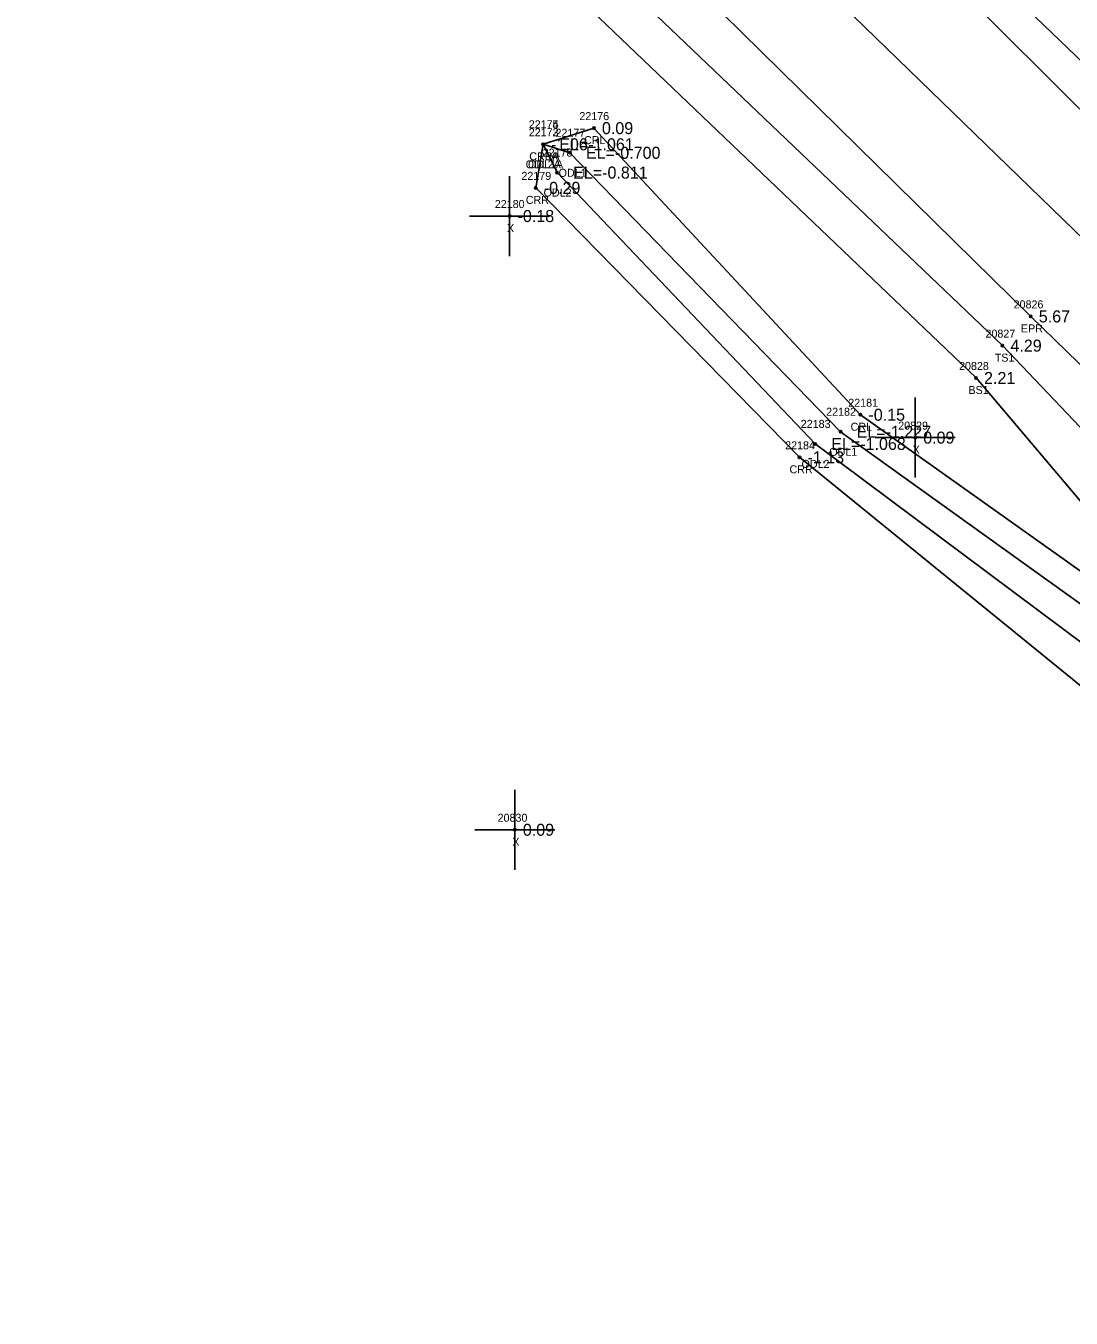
# Model space of a CAD drawing. Extents: x 2608745 to 2610333, y 641917 to 643463.
# Drawn here: x 2609277.1 to 2609407.7, y 642665.2 to 642826.6 of the extents above; entities that cross this region are included whole.
import ezdxf

# ---------------------------------------------------------------- set-up
doc = ezdxf.new("R2010")
doc.units = 0
for name, color, linetype in [('RD_DTM_BkLn1', 7, 'Continuous'), ('RD_DTM_BkLn2', 7, 'Continuous'), ('RD_DTM_BkLn_txCode', 7, 'Continuous'), ('RD_EX_H2O', 7, 'Continuous'), ('RD_EX_H2O_txCode', 7, 'Continuous'), ('RD_EX_Misc', 7, 'Continuous'), ('RD_EX_Misc_txCode', 7, 'Continuous'), ('RD_EX_Road', 7, 'Continuous'), ('RD_EX_Road_txCode', 7, 'Continuous'), ('RD_EX_TX_H2O_ELEV', 7, 'Continuous'), ('RD_EX_TX_Misc_ELEV', 7, 'Continuous'), ('RD_EX_TX_Road_ELEV', 7, 'Continuous'), ('RD_SMD_Locator', 7, 'Continuous')]:
    doc.layers.add(name, color=color, linetype=linetype)

msp = doc.modelspace()

# ---------------------------------------------------------------- linework, layer by layer
at = {"layer": 'RD_DTM_BkLn1'}
msp.add_lwpolyline([(2608814.73, 643373.65), (2608890.45, 643300.26), (2608962.19, 643231.31), (2609034.91, 643161.19), (2609108.48, 643089.9), (2609179.19, 643022.29), (2609255.71, 642948.78), (2609335.19, 642871.73), (2609410.7, 642798.48), (2609491.67, 642719.95), (2609518.07, 642695.15)], dxfattribs=at)
at = {"layer": 'RD_DTM_BkLn2'}
for points in [[(2609298.5, 642957.84), (2609303.58, 642944.57), (2609301.78, 642940.67), (2609288.09, 642950.22), (2609286.42, 642948.37), (2609286.98, 642943.32), (2609297.07, 642935.45), (2609305.3, 642928.41), (2609313.77, 642918.5), (2609346.23, 642882.3), (2609422.21, 642809.45), (2609480.56, 642755.4), (2609506.75, 642733.83), (2609516.79, 642724.84), (2609528.1, 642713.09), (2609531.25, 642709.73), (2609532.97, 642706.82)], [(2609261.87, 642916.52), (2609266.58, 642914.91), (2609285.18, 642896.17), (2609323.43, 642858.86), (2609399.07, 642786.65), (2609450.77, 642732.34), (2609478.69, 642705.43), (2609489.94, 642696.01), (2609499.39, 642685.95), (2609506.29, 642680.17), (2609532.97, 642706.82)], [(2609260.59, 642912.35), (2609267.04, 642908.29), (2609268.14, 642909.06), (2609282.93, 642892.55), (2609320.01, 642855.03), (2609395.77, 642782.61), (2609444.33, 642725.24)]]:
    msp.add_lwpolyline(points, dxfattribs=at)
at = {"layer": 'RD_EX_H2O'}
for points in [[(2609341.7, 642811.8), (2609348.04, 642813.82), (2609381.33, 642778.02), (2609418.14, 642751.86), (2609444.33, 642725.24), (2609470.95, 642698.08), (2609498.28, 642669.79)], [(2609341.7, 642811.8), (2609340.78, 642806.36), (2609373.72, 642772.7), (2609409.62, 642743.52), (2609461.2, 642683.86), (2609477.32, 642664.29)], [(2609341.7, 642811.8), (2609343.44, 642808.27), (2609375.68, 642774.38), (2609412.81, 642746.64), (2609463.49, 642686.63), (2609487.77, 642666.13)], [(2609341.7, 642811.8), (2609345.04, 642810.74), (2609378.85, 642775.89), (2609415.34, 642749.68), (2609465.85, 642691.72), (2609492.22, 642666.66)]]:
    msp.add_lwpolyline(points, dxfattribs=at)
at = {"layer": 'RD_EX_Misc'}
for p, q in [((2609337.5, 642797.84), (2609337.5, 642807.84)), ((2609332.5, 642802.84), (2609342.5, 642802.84)), ((2609388.17, 642770.16), (2609388.17, 642780.16)), ((2609383.17, 642775.16), (2609393.17, 642775.16)), ((2609338.16, 642721.18), (2609338.16, 642731.18)), ((2609333.16, 642726.18), (2609343.16, 642726.18))]:
    msp.add_line(p, q, dxfattribs=at)
at = {"layer": 'RD_EX_Road'}
for points in [[(2608806.89, 643364.99), (2608810.18, 643361.1), (2608820.75, 643351.25), (2608881.81, 643292.24), (2608917.83, 643257.49), (2608933.21, 643242.71), (2608954.07, 643222.83), (2609026.06, 643154.19), (2609039.6, 643139.96), (2609073.88, 643106.95), (2609100.48, 643081.89), (2609124.19, 643058.87), (2609171.61, 643013.71), (2609183.19, 643002.28), (2609197.91, 642988.37), (2609247.59, 642940.95), (2609328.02, 642863.6), (2609402.61, 642790.3), (2609474.23, 642720.69), (2609483.84, 642711.58), (2609495.78, 642699.92), (2609509.81, 642686.45)], [(2609058.51, 643155.46), (2609096.06, 643119.37), (2609116.51, 643099.11), (2609162.4, 643055.35), (2609177.21, 643041.34), (2609188.35, 643030.96), (2609199.91, 643019.76), (2609205.8, 643014.04), (2609217.13, 643003.17), (2609235.83, 642983.9), (2609237.03, 642983.51), (2609256.8, 642965.04), (2609258.49, 642962.51), (2609263.65, 642957.66), (2609344.71, 642879.89), (2609418.83, 642806.19), (2609500.61, 642728.46), (2609512.38, 642716.82), (2609526.19, 642703.5)]]:
    msp.add_lwpolyline(points, dxfattribs=at)
at = {"layer": 'RD_SMD_Locator'}
for centre in [(2609348.04, 642813.82), (2609341.7, 642811.8), (2609341.7, 642811.8), (2609341.7, 642811.8), (2609341.7, 642811.8), (2609345.04, 642810.74), (2609343.44, 642808.27), (2609340.78, 642806.36), (2609337.5, 642802.84), (2609402.61, 642790.3), (2609399.07, 642786.65), (2609395.77, 642782.61), (2609381.33, 642778.02), (2609378.85, 642775.89), (2609375.68, 642774.38), (2609388.17, 642775.16), (2609373.72, 642772.7), (2609338.16, 642726.18)]:
    msp.add_circle(centre, 0.15, dxfattribs=at)

# ---------------------------------------------------------------- texts
at = {"layer": 'RD_DTM_BkLn_txCode'}
for s, p in [('20827', (2609396.95, 642787.65)), ('20828', (2609393.65, 642783.61)), ('TS1', (2609398.11, 642784.65)), ('BS1', (2609394.82, 642780.61))]:
    msp.add_text(s, height=1, dxfattribs=at).set_placement(p)
at = {"layer": 'RD_EX_H2O_txCode'}
for s, p in [('22174', (2609339.9, 642813.8)), ('22175', (2609339.9, 642813.8)), ('22176', (2609346.22, 642814.82)), ('22172', (2609339.9, 642812.8)), ('22173', (2609339.9, 642812.8)), ('22177', (2609343.24, 642812.74)), ('CRL', (2609346.81, 642811.82)), ('CRRA', (2609339.96, 642809.8)), ('CRLA', (2609339.98, 642809.8)), ('22178', (2609341.64, 642810.27)), ('22179', (2609338.98, 642807.36)), ('ODL2A', (2609339.52, 642808.8)), ('ODL1A', (2609339.8, 642808.8)), ('ODL1', (2609343.63, 642807.74)), ('CRR', (2609339.53, 642804.36)), ('ODL2', (2609341.75, 642805.27)), ('22181', (2609379.81, 642779.02)), ('22182', (2609377.05, 642777.89)), ('22183', (2609373.88, 642776.38)), ('CRL', (2609380.1, 642776.02)), ('22184', (2609371.93, 642773.7)), ('ODL1', (2609377.44, 642772.89)), ('CRR', (2609372.47, 642770.7)), ('ODL2', (2609373.98, 642771.38))]:
    msp.add_text(s, height=1, dxfattribs=at).set_placement(p)
at = {"layer": 'RD_EX_Misc_txCode'}
for s, p in [('22180', (2609335.66, 642803.84)), ('X', (2609337.18, 642800.84)), ('20829', (2609386.05, 642776.16)), ('X', (2609387.85, 642773.16)), ('20830', (2609336.01, 642727.18)), ('X', (2609337.85, 642724.18))]:
    msp.add_text(s, height=1, dxfattribs=at).set_placement(p)
at = {"layer": 'RD_EX_Road_txCode'}
for s, p in [('20826', (2609400.47, 642791.3)), ('EPR', (2609401.38, 642788.3))]:
    msp.add_text(s, height=1, dxfattribs=at).set_placement(p)
at = {"layer": 'RD_EX_TX_H2O_ELEV'}
for s, p in [('0.09', (2609349.04, 642813.07)), ('-1.06', (2609342.7, 642811.05)), ('-1.06', (2609342.7, 642811.05)), ('EL=-1.061', (2609343.7, 642811.05)), ('EL=-1.061', (2609343.7, 642811.05)), ('EL=-0.700', (2609347.04, 642809.99)), ('EL=-0.811', (2609345.44, 642807.52)), ('-0.29', (2609341.78, 642805.61)), ('-0.15', (2609382.33, 642777.27)), ('EL=-1.227', (2609380.85, 642775.14)), ('EL=-1.068', (2609377.68, 642773.63)), ('-1.13', (2609374.72, 642771.95))]:
    msp.add_text(s, height=1.5, dxfattribs=at).set_placement(p)
at = {"layer": 'RD_EX_TX_Misc_ELEV'}
for s, p in [('-0.18', (2609338.5, 642802.09)), ('4.29', (2609400.07, 642785.9)), ('2.21', (2609396.77, 642781.86)), ('0.09', (2609389.17, 642774.41)), ('0.09', (2609339.16, 642725.43))]:
    msp.add_text(s, height=1.5, dxfattribs=at).set_placement(p)
at = {"layer": 'RD_EX_TX_Road_ELEV'}
msp.add_text('5.67', height=1.5, dxfattribs=at).set_placement((2609403.61, 642789.55))

doc.saveas('drawing.dxf')
